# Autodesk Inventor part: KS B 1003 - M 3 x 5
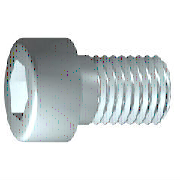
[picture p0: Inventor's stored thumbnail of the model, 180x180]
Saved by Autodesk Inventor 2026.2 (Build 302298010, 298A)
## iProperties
Created: 2025-01
Part Number: KS B 1003 - M 3 x 5
Material: 강철, 연강
Description: 6각머리 태핑 나사
Document SubType Name: Modeling
Standard: KS B 1003
Designer: work
Standards Organization: KS
Language: ko-KR
Size Designation: M 3 x 5
Categories: <MemberInstance><Categories><Category DisplayName="조임쇠" InternalName="e4da775c-781d-43d5-af7c-5136215cf5a6" Mnemonic="FSTN"><Category DisplayName="볼트" InternalN
Density: 7.85 g/cm^3
Appearance: 반연마
IsCustomPart: 1
Author: work
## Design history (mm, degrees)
workplane "Work Plane1"
fillet "Fillet2" dims "d30" = 0.1 (= R)
revolve "본체" stored, may be unused: angle "d10" = 90 deg
sketch "스케치2"
  geometry: L1 (0, -3.85)-(0, 3.85) reference; L2 (-3.85, 0)-(3.85, 0) reference; L3 (1.443, 0)-(0.722, -1.25); L4 (0.722, -1.25)-(-0.722, -1.25); L5 (-0.722, -1.25)-(-1.443, 0); L6 (-1.443, 0)-(-0.722, 1.25); L7 (-0.722, 1.25)-(0.722, 1.25); L8 (0.722, 1.25)-(1.443, 0); 2 further points
  constraints: 12 end point, 1 coincident, 1 horizontal alignment, 1 point on line, 12 other
extrude "슬롯" join sketch "스케치2" stored distance "d11" = 10; taper "d12" = 0 deg
body "Solid1"
fillet "모깎기1" dims "d17" = 0.3 (= RR)
feature "스레드" dims "d13" = 3.75 (= GEL), "d14" = 0
chamfer "모따기1" distance "d15" = 0.30673 (= -0.5 x SPD + 0.5 x GD); stored, may be unused: second distance "d16" = 0.30673 (= GUL), angle "d27" = 45 deg
sketch "스케치1"
  geometry: L1 (-0.867, 0)-(5, 0); L2 (5, 0)-(5, 1.5); L3 (5, 1.5)-(1.25, 1.5); L4 (1.25, 1.5)-(0.943, 1.5); L5 (0.943, 1.5)-(0, 1.5); L6 (0, 1.5)-(0, 2.75); L7 (0, 2.75)-(-3, 2.75); L8 (-3, 2.75)-(-3, 1.443); L9 (-3, 1.443)-(-1.7, 1.443); L10 (-1.7, 1.443)-(-0.867, 0); L11 (-4.6, 0)-(6.6, 0) reference; L12 (0, -0.55)-(0, 3.3) reference; L13 (1.25, 1.5)-(0, 1.5)
  constraints: 22 end point, 6 parallel, 2 collinear, 2 perpendicular, 1 horizontal, 1 point on line
  dimensions: "d1" = 3.75 distance from line of L3.end L2 (= GEL); "d2" = 0.30683 distance of L4.end L3.end (computed from GAL); "d3" = 3 distance between parallel lines of L8 L6 (= KOH); "d4" = 1.3 distance of L8.end L9.end (= INTI); "d5" = 60 deg angle of L10 L1; "d6" = 3 diameter of L3 L1 (= GD); "d7" = 3 diameter of L5 L1 (= BDM); "d8" = 2.88675 diameter of L9 L1 (= 1.1547 x SW); "d9" = 5.5 diameter of L7 L1 (= KOD); "d26" = 5 distance between parallel lines of L12 L2 (= NLG)
other parameters: "GD" = 3 (= NND) [user parameter; used in 2 equation terms], "NLG" = 5 [user parameter; used in 1 equation term], "GEL" = 3.75 [user parameter; used in 2 equation terms], "KOD" = 5.5 [user parameter; used in 1 equation term], "KOH" = 3 [user parameter; used in 1 equation term], "INTI" = 1.3 [user parameter; used in 1 equation term], "GAL" = 0.30673 (= 0.61345 x PTC) [user parameter; used in 1 equation term], "GUL" = 0.30673 (= 0.61345 x PTC) [user parameter; used in 1 equation term], "BDM" = 3 (= NND) [user parameter; used in 1 equation term], "SW" = 2.5 [user parameter; used in 2 equation terms], "RR" = 0.3 [user parameter; used in 1 equation term], "SPD" = 2.38655 (= NND - 1.2269 x PTC) [user parameter; used in 1 equation term], "d19" = 0, "d28" = 0, "d29" = 0, "R" = 0.1 [user parameter; used in 1 equation term], "PHH" = 0.1 [user parameter], "GD1" = 2.38655 (= THREADDIA - 1.2269 x PTC) [user parameter], "THREADDIA" = 3 [user parameter; used in 1 equation term], "FAWI" = 45 deg [user parameter], "PTC" = 0.5 [user parameter; used in 5 equation terms], "NND" = 3 [user parameter; used in 3 equation terms], "TOA" = 30 deg [user parameter], "E0" = 2.8875 (= 1.155 x SW) [user parameter]
